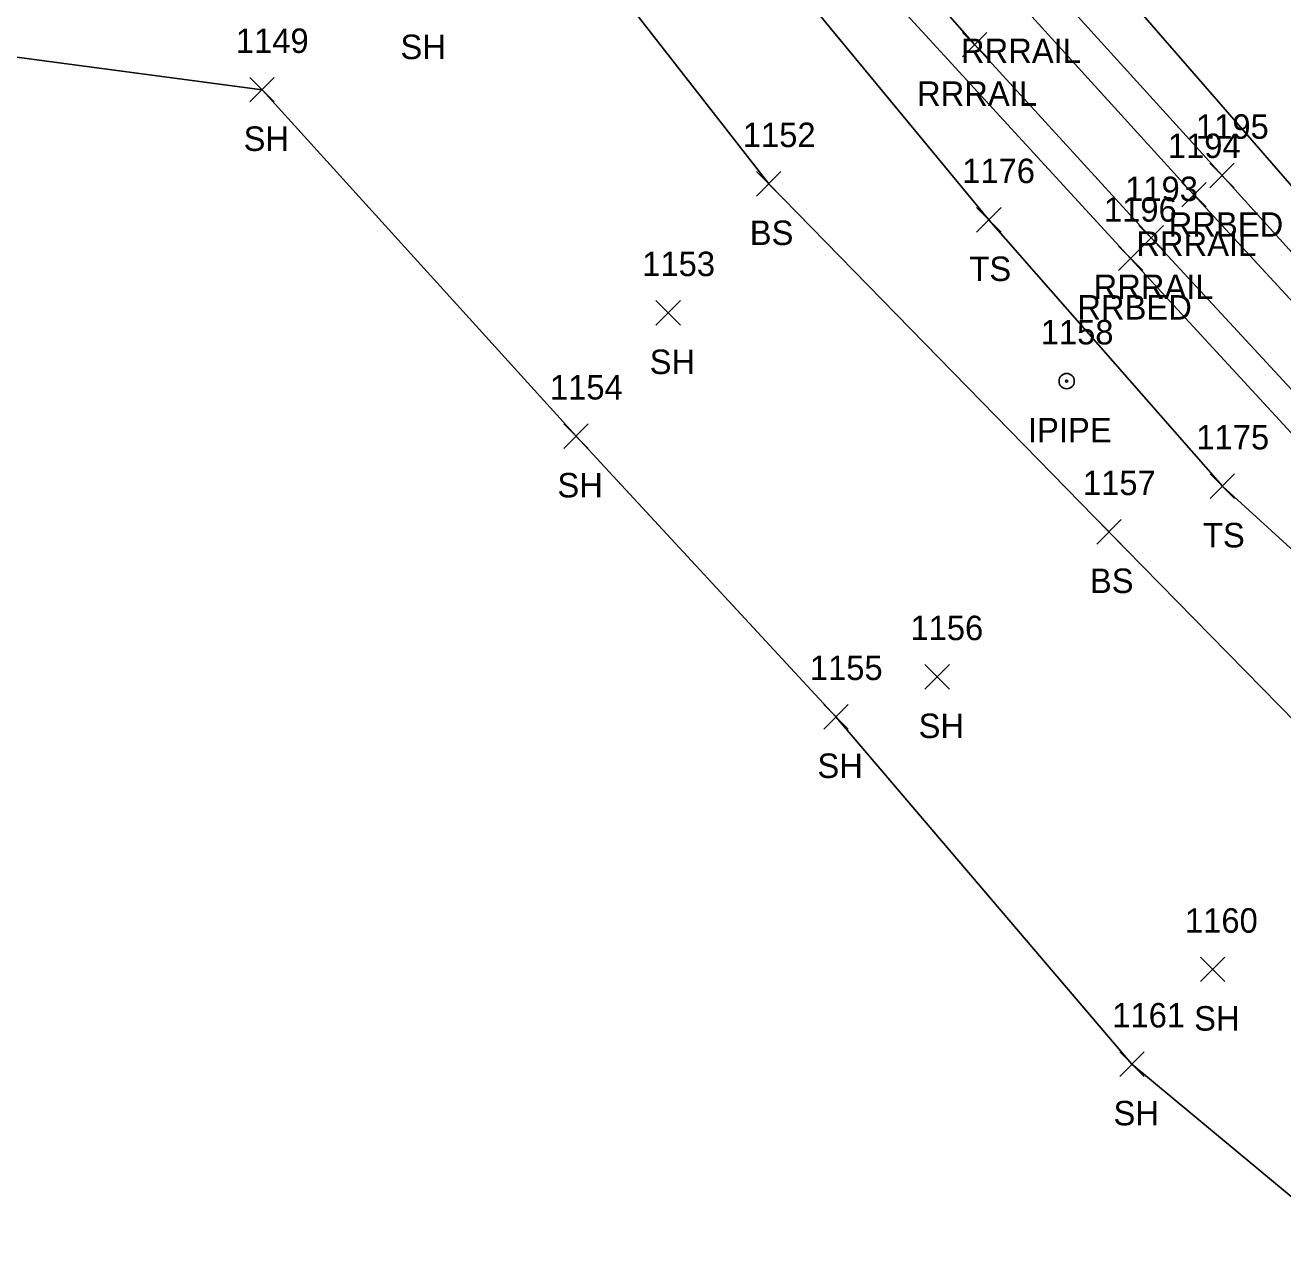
# Model space of a CAD drawing. Extents: x 1679360 to 1685861, y 903420 to 905946.
# Drawn here: x 1679830.3 to 1679933.1, y 903832.2 to 903931.8 of the extents above; entities that cross this region are included whole.
import ezdxf

# ---------------------------------------------------------------- set-up
doc = ezdxf.new("R2010")
doc.units = 0
for name, color, linetype in [('L_A', 7, 'Continuous'), ('L_I', 7, 'Continuous'), ('L_TIC', 7, 'Continuous'), ('LELB', 7, 'Continuous'), ('LSOGP', 7, 'Continuous'), ('M_A', 7, 'Continuous'), ('M_I', 7, 'Continuous'), ('MPIP', 7, 'Continuous'), ('R_A', 7, 'Continuous'), ('R_I', 7, 'Continuous'), ('R_TIC', 7, 'Continuous'), ('RR', 7, 'Continuous'), ('RRB', 7, 'Continuous')]:
    doc.layers.add(name, color=color, linetype=linetype)

msp = doc.modelspace()

# ---------------------------------------------------------------- linework, layer by layer
at = {"layer": 'L_TIC'}
for points in [[(1679848.71, 903925.51), (1679850.71, 903927.51)], [(1679850.71, 903925.51), (1679848.71, 903927.51)], [(1679890.12, 903917.82), (1679892.12, 903919.82)], [(1679892.12, 903917.82), (1679890.12, 903919.82)], [(1679908.11, 903914.88), (1679910.11, 903916.88)], [(1679910.11, 903914.88), (1679908.11, 903916.88)], [(1679881.9, 903907.28), (1679883.9, 903909.28)], [(1679883.9, 903907.28), (1679881.9, 903909.28)], [(1679874.37, 903897.2), (1679876.37, 903899.2)], [(1679876.37, 903897.2), (1679874.37, 903899.2)], [(1679927.2, 903893.12), (1679929.2, 903895.12)], [(1679929.2, 903893.12), (1679927.2, 903895.12)], [(1679917.93, 903889.39), (1679919.93, 903891.39)], [(1679919.93, 903889.39), (1679917.93, 903891.39)], [(1679903.89, 903877.54), (1679905.89, 903879.54)], [(1679905.89, 903877.54), (1679903.89, 903879.54)], [(1679895.61, 903874.28), (1679897.61, 903876.28)], [(1679897.61, 903874.28), (1679895.61, 903876.28)], [(1679926.4, 903853.64), (1679928.4, 903855.64)], [(1679928.4, 903853.64), (1679926.4, 903855.64)], [(1679919.81, 903845.9), (1679921.81, 903847.9)], [(1679921.81, 903845.9), (1679919.81, 903847.9)]]:
    msp.add_lwpolyline(points, dxfattribs=at)
at = {"layer": 'LELB'}
for points in [[(1680042.48, 903807.68), (1680020.07, 903831.14), (1679994.57, 903854.85), (1679973.52, 903877.19), (1679947.49, 903902.98), (1679918.08, 903936.81), (1679895.51, 903960.77), (1679875.1, 903984.26)], [(1679854.83, 903964.92), (1679872.81, 903942.29), (1679891.12, 903918.82), (1679918.93, 903890.39), (1679939.76, 903869.14), (1679968.6, 903838.01), (1679992.84, 903818.01), (1680020.69, 903787.69)], [(1680027, 903796.8), (1680001.4, 903822.24), (1679984.38, 903839.7), (1679957.18, 903867.74), (1679928.2, 903894.12), (1679909.11, 903915.88), (1679887.98, 903941.49), (1679868.32, 903960.05)]]:
    msp.add_lwpolyline(points, dxfattribs=at)
at = {"layer": 'LSOGP'}
msp.add_lwpolyline([(1679809.97, 903931.78), (1679849.71, 903926.51), (1679875.37, 903898.2), (1679896.61, 903875.28), (1679920.81, 903846.9), (1679951.04, 903821.8)], dxfattribs=at)
at = {"layer": 'MPIP'}
for radius in [0.625, 0.0833]:
    msp.add_circle((1679915.47, 903902.7), radius, dxfattribs=at)
at = {"layer": 'R_TIC'}
for points in [[(1679906.95, 903929.19), (1679908.95, 903931.19)], [(1679908.95, 903929.19), (1679906.95, 903931.19)], [(1679927.17, 903918.5), (1679929.17, 903920.5)], [(1679929.17, 903918.5), (1679927.17, 903920.5)], [(1679924.87, 903916.93), (1679926.87, 903918.93)], [(1679926.87, 903916.93), (1679924.87, 903918.93)], [(1679921.38, 903913.41), (1679923.38, 903915.41)], [(1679923.38, 903913.41), (1679921.38, 903915.41)], [(1679919.7, 903911.73), (1679921.7, 903913.73)], [(1679921.7, 903911.73), (1679919.7, 903913.73)]]:
    msp.add_lwpolyline(points, dxfattribs=at)
at = {"layer": 'RR'}
for points in [[(1679824.64, 904028.72), (1679837.34, 904012.39), (1679861.93, 903982.57), (1679878.2, 903963.7), (1679892.43, 903947.81), (1679907.95, 903930.19), (1679922.38, 903914.41), (1679937.85, 903897.68), (1679952.05, 903882.52), (1679968.97, 903864.98), (1679984.51, 903848.78), (1680002.83, 903830.07), (1680018.62, 903814.03), (1680033.05, 903799.46), (1680047.5, 903784.67), (1680062.83, 903769.48), (1680079.58, 903752.46), (1680095.32, 903736.48)], [(1679831.29, 904028.45), (1679844.1, 904012.06), (1679865.83, 903985.59), (1679882.11, 903966.82), (1679896.05, 903950.91), (1679911.54, 903933.69), (1679925.87, 903917.93), (1679941.58, 903900.91), (1679955.49, 903886.24), (1679972.28, 903868.6), (1679988.05, 903852.2), (1680006.22, 903833.3), (1680022.22, 903817.37), (1680036.49, 903802.97), (1680051.11, 903788.21), (1680066.39, 903772.91), (1680082.82, 903756.11), (1680099.28, 903739.48)]]:
    msp.add_lwpolyline(points, dxfattribs=at)
at = {"layer": 'RRB'}
for points in [[(1679852.8, 904005.56), (1679867.15, 903987.02), (1679898.43, 903952.3), (1679928.17, 903919.5), (1679957.86, 903886.73), (1679990.5, 903854.15), (1680024.93, 903818.74), (1680038.52, 903804.88)], [(1679840.74, 904004.22), (1679860.45, 903979.99), (1679889.94, 903946.25), (1679920.7, 903912.73), (1679950.15, 903880.79), (1679982.32, 903846.88), (1680017.14, 903812.2), (1680030.44, 903798.07)]]:
    msp.add_lwpolyline(points, dxfattribs=at)

# ---------------------------------------------------------------- texts
at = {"layer": 'L_A'}
for s, p in [('SH', (1679861.02, 903929.01)), ('SH', (1679848.2, 903921.51)), ('BS', (1679889.57, 903913.82)), ('TS', (1679907.52, 903910.88)), ('SH', (1679881.39, 903903.28)), ('SH', (1679873.85, 903893.2)), ('TS', (1679926.61, 903889.12)), ('BS', (1679917.37, 903885.39)), ('SH', (1679903.37, 903873.54)), ('SH', (1679895.1, 903870.28)), ('SH', (1679925.89, 903849.64)), ('SH', (1679919.3, 903841.9))]:
    msp.add_text(s, height=2, dxfattribs=at).set_placement(p)
at = {"layer": 'L_I'}
for s, p in [('1149', (1679847.57, 903929.51)), ('1152', (1679889, 903921.82)), ('1176', (1679906.93, 903918.88)), ('1153', (1679880.78, 903911.28)), ('1154', (1679873.24, 903901.2)), ('1175', (1679926.07, 903897.12)), ('1157', (1679916.8, 903893.39)), ('1156', (1679902.7, 903881.54)), ('1155', (1679894.48, 903878.28)), ('1160', (1679925.14, 903857.64)), ('1161', (1679919.2, 903849.9))]:
    msp.add_text(s, height=2, dxfattribs=at).set_placement(p)
at = {"layer": 'M_A'}
msp.add_text('IPIPE', height=2, dxfattribs=at).set_placement((1679912.31, 903897.7))
at = {"layer": 'M_I'}
msp.add_text('1158', height=2, dxfattribs=at).set_placement((1679913.35, 903905.7))
at = {"layer": 'R_A'}
for s, p in [('RRRAIL', (1679906.83, 903928.69)), ('RRRAIL', (1679903.24, 903925.19)), ('RRBED', (1679923.81, 903914.5)), ('RRRAIL', (1679921.16, 903912.93)), ('RRRAIL', (1679917.67, 903909.41)), ('RRBED', (1679916.34, 903907.73))]:
    msp.add_text(s, height=2, dxfattribs=at).set_placement(p)
at = {"layer": 'R_I'}
for s, p in [('1195', (1679926.04, 903922.5)), ('1194', (1679923.74, 903920.93)), ('1193', (1679920.25, 903917.41)), ('1196', (1679918.52, 903915.73))]:
    msp.add_text(s, height=2, dxfattribs=at).set_placement(p)

doc.saveas('drawing.dxf')
